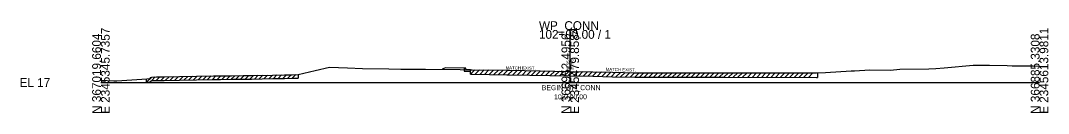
# Model space of a CAD drawing. Extents: x -26 to 2345577, y -10 to 367097.
# Drawn here: x -25.7 to 302.8, y 1490.3 to 1519.6 of the extents above; entities that cross this region are included whole.
import ezdxf

# ---------------------------------------------------------------- set-up
doc = ezdxf.new("R2010")
doc.units = 0
for name, color, linetype in [('RD_GPK_XS_Cell', 7, 'Continuous'), ('RD_XS_Base', 7, 'Continuous'), ('RD_XS_CurbTop', 7, 'Continuous'), ('RD_XS_EarthShd', 7, 'Continuous'), ('RD_XS_ExGround', 7, 'Continuous'), ('RD_XS_ExPaveRet', 7, 'Continuous'), ('RD_XS_TieSlope', 7, 'Continuous'), ('RD_XS_TX_Elev_EX', 7, 'Continuous'), ('RD_XS_TX_Elev_PR', 7, 'Continuous'), ('RD_XS_TX_Slope', 7, 'Continuous'), ('RD_XS_TX_Station', 7, 'Continuous'), ('RD_XS_TX_TOC', 7, 'Continuous')]:
    doc.layers.add(name, color=color, linetype=linetype)

msp = doc.modelspace()

# ---------------------------------------------------------------- linework, layer by layer
at = {"layer": 'RD_GPK_XS_Cell'}
for p, q in [((150, 1500), (150, 1516.74)), ((0, 1500), (150, 1500)), ((150, 1500), (300, 1500))]:
    msp.add_line(p, q, dxfattribs=at)
at = {"layer": 'RD_XS_Base'}
for p, q in [((116.1, 1504.59), (116.1, 1503.59)), ((116.1, 1503.59), (116.6, 1503.59)), ((116.6, 1503.59), (118.1, 1503.57)), ((118.1, 1503.57), (118.1, 1504.07))]:
    msp.add_line(p, q, dxfattribs=at)
at = {"layer": 'RD_XS_CurbTop'}
for p, q in [((116.6, 1504.59), (116.1, 1504.59)), ((116.69, 1504.09), (116.6, 1504.59)), ((118.1, 1504.07), (116.69, 1504.09)), ((118.1, 1504.09), (118.1, 1504.07))]:
    msp.add_line(p, q, dxfattribs=at)
at = {"layer": 'RD_XS_EarthShd'}
msp.add_line((116.1, 1504.59), (110.1, 1504.71), dxfattribs=at)
at = {"layer": 'RD_XS_ExGround'}
msp.add_lwpolyline([(0, 1500.73), (4.16, 1500.56), (5.06, 1500.58), (14.63, 1501.22), (15.75, 1501.23), (15.92, 1501.58), (16.31, 1501.73), (17.8, 1501.77), (20.21, 1501.83), (25.1, 1501.93), (36, 1502.09), (38.24, 1502.13), (41.71, 1502.17), (45.5, 1502.21), (48.1, 1502.24), (54.98, 1502.39), (58.62, 1502.4), (61.13, 1502.49), (63.04, 1502.53), (68.44, 1503.78), (73.02, 1504.87), (78.85, 1504.65), (83.58, 1504.46), (91.99, 1504.35), (95.86, 1504.28), (103.77, 1504.26), (114.79, 1504.15), (118.1, 1504.09), (118.65, 1504.07), (129.77, 1503.91), (130.18, 1503.9), (130.54, 1503.89), (150, 1503.55), (157.24, 1503.42), (163.52, 1503.28), (170.65, 1503.12), (199.22, 1503.1), (228.67, 1503.07), (231.62, 1503.21), (239.83, 1503.69), (240.21, 1503.71), (240.86, 1503.77), (245.78, 1504.06), (252.39, 1503.96), (255.34, 1504.23), (264.56, 1504.41), (266.88, 1504.47), (269.55, 1504.71), (278.81, 1505.49), (283.96, 1505.58), (289.64, 1505.44), (291.28, 1505.35), (294.04, 1505.31), (297.91, 1505.31), (300, 1505.19)], dxfattribs=at)
at = {"layer": 'RD_XS_ExPaveRet'}
for p, q in [((14.61, 1500.08), (16.24, 1501.71)), ((16.11, 1500.51), (17.36, 1501.76)), ((17.61, 1500.62), (18.79, 1501.8)), ((19.11, 1500.66), (20.29, 1501.84)), ((20.61, 1500.7), (21.78, 1501.86)), ((22.11, 1500.73), (23.28, 1501.89)), ((23.61, 1500.76), (24.78, 1501.92)), ((25.11, 1500.79), (26.27, 1501.95)), ((26.61, 1500.81), (27.77, 1501.97)), ((28.11, 1500.83), (29.27, 1501.99)), ((29.61, 1500.85), (30.77, 1502.01)), ((31.11, 1500.87), (32.27, 1502.03)), ((32.61, 1500.89), (33.77, 1502.05)), ((34.11, 1500.92), (35.27, 1502.08)), ((35.61, 1500.94), (36.77, 1502.1)), ((37.11, 1500.96), (38.28, 1502.13)), ((38.61, 1500.99), (39.77, 1502.15)), ((40.11, 1501.01), (41.27, 1502.16)), ((41.61, 1501.03), (42.77, 1502.18)), ((43.11, 1501.04), (44.27, 1502.2)), ((44.61, 1501.06), (45.77, 1502.21)), ((46.11, 1501.07), (47.27, 1502.23)), ((47.61, 1501.09), (48.78, 1502.26)), ((49.11, 1501.12), (50.28, 1502.29)), ((50.61, 1501.15), (51.78, 1502.32)), ((52.11, 1501.19), (53.28, 1502.35)), ((53.61, 1501.22), (54.78, 1502.39)), ((55.11, 1501.25), (56.26, 1502.4)), ((56.61, 1501.25), (57.76, 1502.4)), ((58.11, 1501.26), (59.28, 1502.43)), ((59.61, 1501.29), (60.8, 1502.48)), ((61.11, 1501.35), (62.28, 1502.51)), ((63.04, 1502.53), (63.04, 1501.39)), ((118.1, 1502.65), (118.1, 1504.09)), ((118.1, 1502.65), (119.51, 1504.06)), ((118.1, 1502.65), (118.65, 1502.63)), ((118.65, 1502.63), (129.77, 1502.47)), ((119.6, 1502.62), (121.02, 1504.03)), ((121.1, 1502.6), (122.52, 1504.01)), ((122.6, 1502.57), (124.02, 1503.99)), ((124.1, 1502.55), (125.52, 1503.97)), ((125.6, 1502.53), (127.02, 1503.95)), ((127.1, 1502.51), (128.52, 1503.92)), ((128.6, 1502.49), (130.02, 1503.9)), ((129.77, 1502.47), (130.18, 1502.46)), ((130.1, 1502.46), (131.52, 1503.88)), ((130.18, 1502.46), (130.54, 1502.46)), ((130.54, 1502.46), (150, 1502.11)), ((131.6, 1502.44), (133.02, 1503.85)), ((133.1, 1502.41), (134.52, 1503.82)), ((134.6, 1502.38), (136.02, 1503.8)), ((136.1, 1502.36), (137.52, 1503.77)), ((137.6, 1502.33), (139.02, 1503.74)), ((139.1, 1502.3), (140.52, 1503.72)), ((140.6, 1502.28), (142.02, 1503.69)), ((142.1, 1502.25), (143.52, 1503.66)), ((143.6, 1502.22), (145.02, 1503.63)), ((145.1, 1502.2), (146.52, 1503.61)), ((146.6, 1502.17), (148.02, 1503.58)), ((148.1, 1502.14), (149.52, 1503.55)), ((149.6, 1502.12), (151.02, 1503.53)), ((150, 1502.11), (157.24, 1501.98)), ((151.1, 1502.09), (152.52, 1503.5)), ((152.6, 1502.06), (154.02, 1503.47)), ((154.1, 1502.04), (155.52, 1503.45)), ((155.6, 1502.01), (157.02, 1503.42)), ((157.1, 1501.98), (158.51, 1503.39)), ((157.24, 1501.98), (163.52, 1501.84)), ((158.6, 1501.95), (160.01, 1503.36)), ((160.1, 1501.92), (161.51, 1503.32)), ((161.6, 1501.88), (163.01, 1503.29)), ((163.1, 1501.85), (164.51, 1503.26)), ((163.52, 1501.84), (170.65, 1501.69)), ((164.6, 1501.82), (166.01, 1503.22)), ((166.1, 1501.79), (167.51, 1503.19)), ((167.6, 1501.75), (169.01, 1503.16)), ((169.1, 1501.72), (170.51, 1503.13)), ((170.6, 1501.69), (172.04, 1503.12)), ((170.65, 1501.69), (199.22, 1501.66)), ((172.1, 1501.68), (173.54, 1503.12)), ((173.6, 1501.68), (175.04, 1503.12)), ((175.1, 1501.68), (176.54, 1503.12)), ((176.6, 1501.68), (178.04, 1503.12)), ((178.1, 1501.68), (179.54, 1503.11)), ((179.6, 1501.68), (181.04, 1503.11)), ((181.1, 1501.68), (182.54, 1503.11)), ((182.6, 1501.68), (184.04, 1503.11)), ((184.1, 1501.67), (185.54, 1503.11)), ((185.6, 1501.67), (187.04, 1503.11)), ((187.1, 1501.67), (188.54, 1503.11)), ((188.6, 1501.67), (190.04, 1503.11)), ((190.1, 1501.67), (191.54, 1503.1)), ((191.6, 1501.67), (193.04, 1503.1)), ((193.1, 1501.67), (194.54, 1503.1)), ((194.6, 1501.67), (196.04, 1503.1)), ((196.1, 1501.66), (197.54, 1503.1)), ((197.6, 1501.66), (199.04, 1503.1)), ((199.1, 1501.66), (200.54, 1503.1)), ((199.22, 1501.66), (228.67, 1501.63)), ((200.6, 1501.66), (202.04, 1503.1)), ((202.1, 1501.66), (203.54, 1503.09)), ((203.6, 1501.66), (205.04, 1503.09)), ((205.1, 1501.66), (206.54, 1503.09)), ((206.6, 1501.65), (208.04, 1503.09)), ((208.1, 1501.65), (209.54, 1503.09)), ((209.6, 1501.65), (211.04, 1503.09)), ((211.1, 1501.65), (212.54, 1503.08)), ((212.6, 1501.65), (214.04, 1503.08)), ((214.1, 1501.65), (215.54, 1503.08)), ((215.6, 1501.64), (217.04, 1503.08)), ((217.1, 1501.64), (218.54, 1503.08)), ((218.6, 1501.64), (220.04, 1503.08)), ((220.1, 1501.64), (221.54, 1503.08)), ((221.6, 1501.64), (223.04, 1503.07)), ((223.1, 1501.64), (224.54, 1503.07)), ((224.6, 1501.64), (226.04, 1503.07)), ((226.1, 1501.63), (227.54, 1503.07)), ((228.67, 1501.63), (228.98, 1501.65)), ((228.98, 1503.08), (228.98, 1501.65)), ((14.61, 1500.08), (14.61, 1501.22)), ((14.61, 1500.08), (14.63, 1500.08)), ((14.63, 1500.08), (15.75, 1500.09)), ((15.75, 1500.09), (15.92, 1500.44)), ((15.92, 1500.44), (16.31, 1500.59)), ((16.31, 1500.59), (17.8, 1500.63)), ((17.8, 1500.63), (20.21, 1500.69)), ((20.21, 1500.69), (25.1, 1500.78)), ((25.1, 1500.78), (36, 1500.94)), ((36, 1500.94), (38.24, 1500.98)), ((38.24, 1500.98), (41.71, 1501.03)), ((41.71, 1501.03), (45.5, 1501.07)), ((45.5, 1501.07), (48.1, 1501.1)), ((48.1, 1501.1), (54.98, 1501.25)), ((54.98, 1501.25), (58.62, 1501.26)), ((58.62, 1501.26), (61.13, 1501.35)), ((61.13, 1501.35), (63.04, 1501.39))]:
    msp.add_line(p, q, dxfattribs=at)
at = {"layer": 'RD_XS_TieSlope'}
msp.add_line((110.1, 1504.71), (109.11, 1504.21), dxfattribs=at)

# ---------------------------------------------------------------- texts
at = {"layer": 'RD_GPK_XS_Cell'}
for s, p in [('WP_CONN', (140, 1516.74)), ('102+00.00 / 1', (140, 1513.94)), ('EL 17', (-26, 1498.6))]:
    msp.add_text(s, height=2.8, dxfattribs=at).set_placement(p)
for s, p in [('N 367019.6604', (0, 1490)), ('E 2345345.7357', (2.8, 1490)), ('N 366952.4956', (150, 1490)), ('E 2345479.8584', (152.8, 1490)), ('N 366885.3308', (300, 1490)), ('E 2345613.9811', (302.8, 1490))]:
    msp.add_text(s, height=2.8, rotation=90, dxfattribs=at).set_placement(p)
at = {"layer": 'RD_XS_TX_Elev_EX'}
msp.add_text('20.55', height=1, rotation=90, dxfattribs=at).set_placement((149.82, 1503.59))
at = {"layer": 'RD_XS_TX_Elev_PR'}
msp.add_text(' 20.55', height=1, rotation=90, dxfattribs=at).set_placement((151, 1503.66))
at = {"layer": 'RD_XS_TX_Slope'}
for rotation, p in [(359.2361, (129.31, 1504.19)), (358.8542, (161.31, 1503.69))]:
    msp.add_text('MATCH EXIST.', height=1, rotation=rotation, dxfattribs=at).set_placement(p)
at = {"layer": 'RD_XS_TX_Station'}
for s, p in [('BEGIN WP_CONN', (140.89, 1497.56)), ('102+00.00', (144.83, 1494.66))]:
    msp.add_text(s, height=1.6, dxfattribs=at).set_placement(p)
at = {"layer": 'RD_XS_TX_TOC'}
msp.add_text('TOCLT', height=0.05, dxfattribs=at).set_placement((116.65, 1504.54))

doc.saveas('drawing.dxf')
